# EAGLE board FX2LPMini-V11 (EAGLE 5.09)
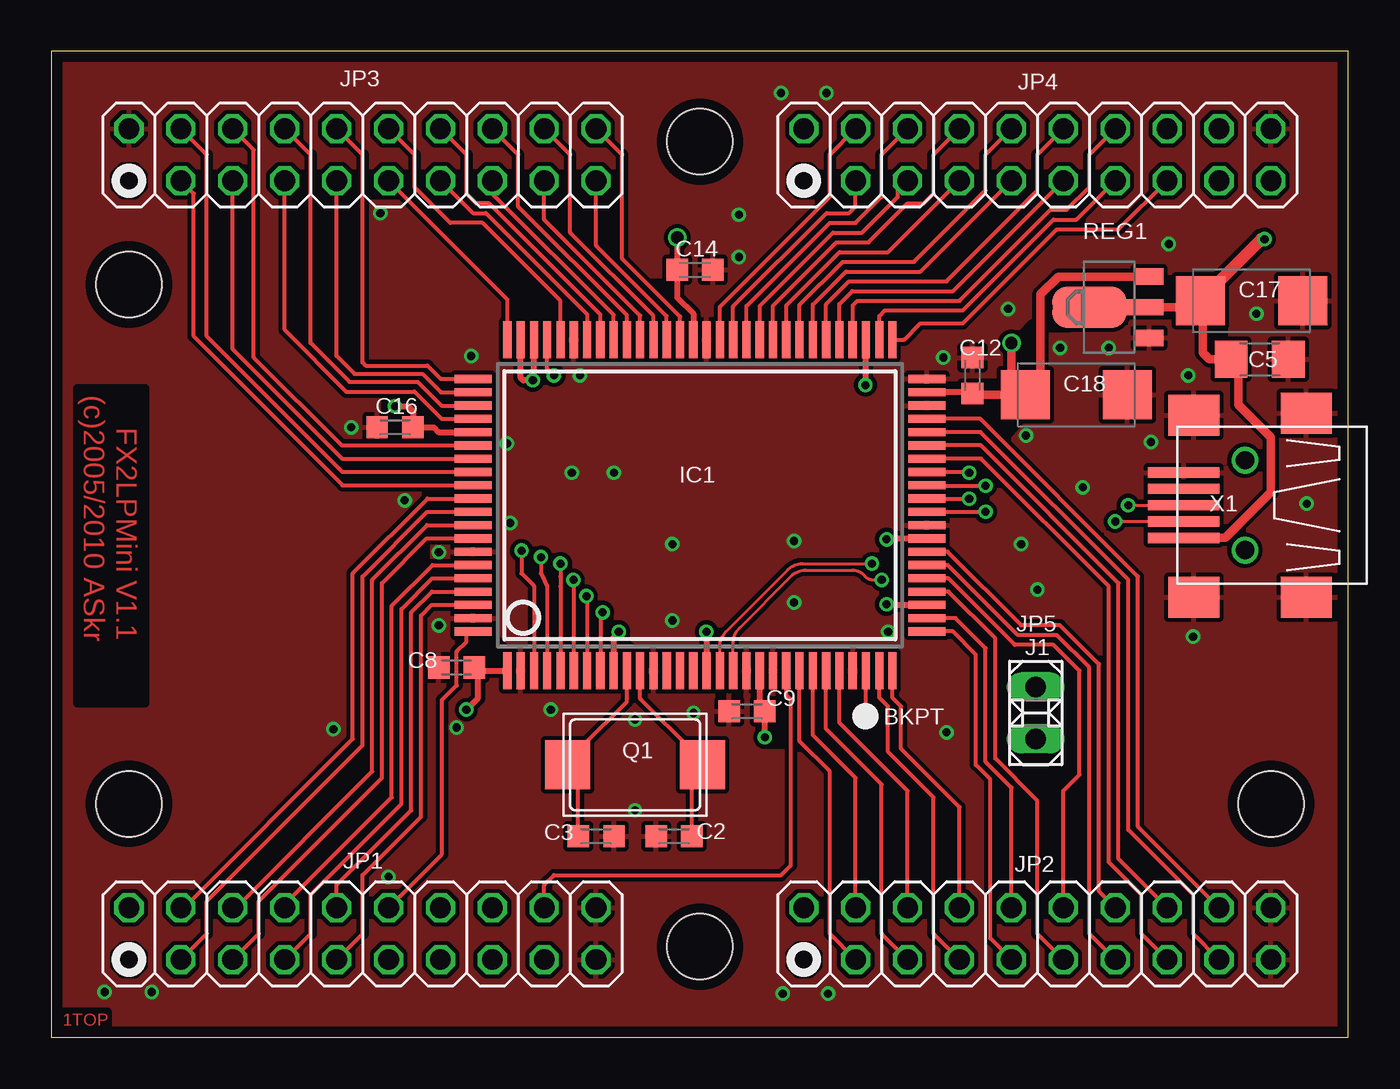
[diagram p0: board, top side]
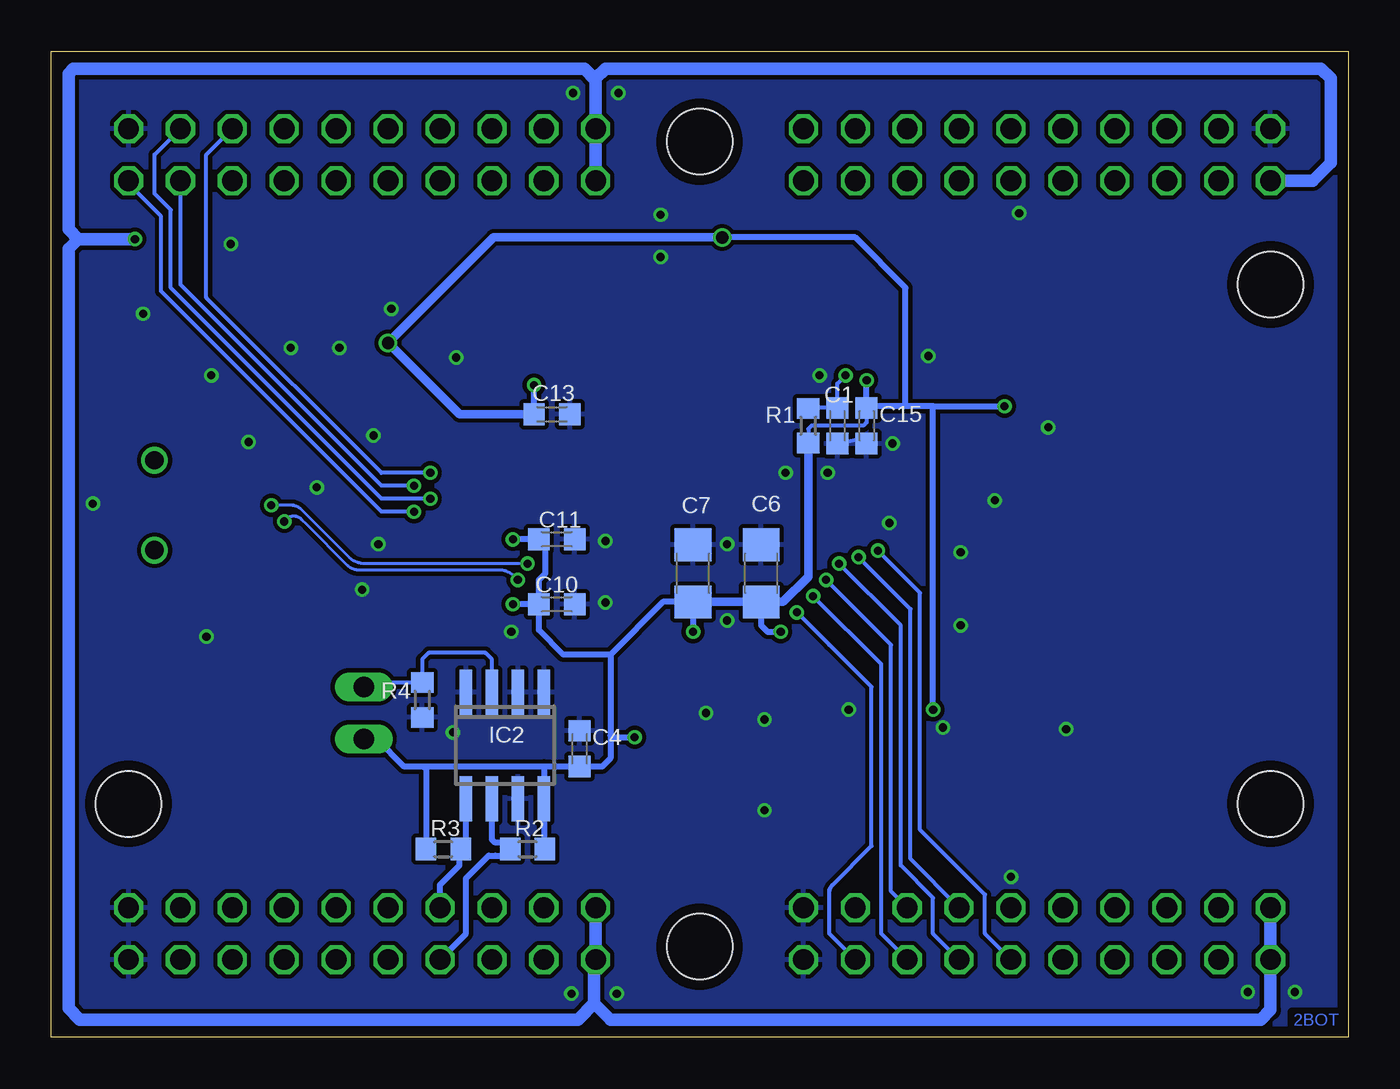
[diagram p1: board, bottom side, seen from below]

Size 63.48 x 48.25 mm. Coordinates in mm from the lower left corner, seen from the top.
Outline: 0,0 63.48,0 63.48,48.25 0,48.25 0,0
Copper layers (1*16): Top 0.035mm / dielectric 1.5mm / Bottom 0.035mm
Design rules "pcb-pool-2009": minimum track width 6mil, minimum drill 12mil, track to track 6mil, track to pad 6mil, pad to pad 6mil, via to via 6mil, smd to smd 6mil, copper to edge 20mil, drill to drill 8mil, minimum pad ring 8mil, minimum via ring 6mil, stop-mask expansion 3mil, vias tented up to drill 0mil, thermal gap 8mil
Holes 3.2 mm at 3.81,36.83 3.81,11.43 59.69,11.43 31.75,43.81 31.75,4.45
tRestrict: 25 lines
bRestrict: 5 lines

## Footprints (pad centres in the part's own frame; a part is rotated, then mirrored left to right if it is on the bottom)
B1,27 = smd 1.27 x 1.27: TP 0,0
C0603K = smd 1.05 x 1.08: 1 -0.875,0; 2 0.875,0
C1206 = smd 1.6 x 1.8: 1 -1.4,0; 2 1.4,0
SMC_C = smd 2.4 x 2.4: + -2.5,0; - 2.5,0
SQFP-R-14X20-100 = smd 0.4 x 1.8: 1 -9.425,-8.1; 2 -8.775,-8.1; 3 -8.125,-8.1; 4 -7.475,-8.1; 5 -6.825,-8.1; 6 -6.175,-8.1; 7 -5.525,-8.1; 8 -4.875,-8.1; 9 -4.225,-8.1; 10 -3.575,-8.1; 11 -2.925,-8.1; 12 -2.275,-8.1; 13 -1.625,-8.1; 14 -0.975,-8.1; 15 -0.325,-8.1; 16 0.325,-8.1; 17 0.975,-8.1; 18 1.625,-8.1; 19 2.275,-8.1; 20 2.925,-8.1; 21 3.575,-8.1; 22 4.225,-8.1; 23 4.875,-8.1; 24 5.525,-8.1; 25 6.175,-8.1; 26 6.825,-8.1; 27 7.475,-8.1; 28 8.125,-8.1; 29 8.775,-8.1; 30 9.425,-8.1; 51 9.425,8.1; 52 8.775,8.1; 53 8.125,8.1; 54 7.475,8.1; 55 6.825,8.1; 56 6.175,8.1; 57 5.525,8.1; 58 4.875,8.1; 59 4.225,8.1; 60 3.575,8.1; 61 2.925,8.1; 62 2.275,8.1; 63 1.625,8.1; 64 0.975,8.1; 65 0.325,8.1; 66 -0.325,8.1; 67 -0.975,8.1; 68 -1.625,8.1; 69 -2.275,8.1; 70 -2.925,8.1; 71 -3.575,8.1; 72 -4.225,8.1; 73 -4.875,8.1; 74 -5.525,8.1; 75 -6.175,8.1; 76 -6.825,8.1; 77 -7.475,8.1; 78 -8.125,8.1; 79 -8.775,8.1; 80 -9.425,8.1 | smd 1.8 x 0.4: 31 11.1,-6.175; 32 11.1,-5.525; 33 11.1,-4.875; 34 11.1,-4.225; 35 11.1,-3.575; 36 11.1,-2.925; 37 11.1,-2.275; 38 11.1,-1.625; 39 11.1,-0.975; 40 11.1,-0.325; 41 11.1,0.325; 42 11.1,0.975; 43 11.1,1.625; 44 11.1,2.275; 45 11.1,2.925; 46 11.1,3.575; 47 11.1,4.225; 48 11.1,4.875; 49 11.1,5.525; 50 11.1,6.175; 81 -11.1,6.175; 82 -11.1,5.525; 83 -11.1,4.875; 84 -11.1,4.225; 85 -11.1,3.575; 86 -11.1,2.925; 87 -11.1,2.275; 88 -11.1,1.625; 89 -11.1,0.975; 90 -11.1,0.325; 91 -11.1,-0.325; 92 -11.1,-0.975; 93 -11.1,-1.625; 94 -11.1,-2.275; 95 -11.1,-2.925; 96 -11.1,-3.575; 97 -11.1,-4.225; 98 -11.1,-4.875; 99 -11.1,-5.525; 100 -11.1,-6.175
SO-08 = smd 0.6 x 2.2: 1 -1.905,-2.6; 2 -0.635,-2.6; 3 0.635,-2.6; 4 1.905,-2.6; 5 1.905,2.6; 6 0.635,2.6; 7 -0.635,2.6; 8 -1.905,2.6
2X10 = drill 1.016 octagon: 1 -11.43,-1.27; 2 -11.43,1.27; 3 -8.89,-1.27; 4 -8.89,1.27; 5 -6.35,-1.27; 6 -6.35,1.27; 7 -3.81,-1.27; 8 -3.81,1.27; 9 -1.27,-1.27; 10 -1.27,1.27; 11 1.27,-1.27; 12 1.27,1.27; 13 3.81,-1.27; 14 3.81,1.27; 15 6.35,-1.27; 16 6.35,1.27; 17 8.89,-1.27; 18 8.89,1.27; 19 11.43,-1.27; 20 11.43,1.27
1X02 = drill 1.016 long: 1 -1.27,0; 2 1.27,0
AKKI_HLX-DB = smd 2.2 x 2.4: P$1 -3.3,0; P$2 3.3,0
R0603 = smd 1 x 1.1: 1 -0.85,0; 2 0.85,0
SOT89 = smd 0.8 x 1.4: 1 -1.499,-1.981; 3 1.499,-1.981 | smd 0.8 x 1.9: 2 0,-1.727 | smd 2.032 x 3.65: 2@1 0,0.94
USB-MB-S = smd 3.5 x 0.5: D+ 3,0; D- 3,0.8; GND 3,-1.6; ID 3,-0.8; VBUS 3,1.6 | smd 2.5 x 2: GND@1 -3,4.5; GND@2 2.5,4.5; GND@3 -3,-4.5; GND@4 2.5,-4.4 | drill 0.9 round: P$5 0,2.2; P$6 0,-2.2

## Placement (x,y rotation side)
BKPT  [B1,27]  39.85,15.72 0 top
C1  100n  [C0603K]  25,29.92 90 bottom
C2  15p  [C0603K]  30.48,9.84 0 top
C3  15p  [C0603K]  26.67,9.84 180 top
C4  100n  [C0603K]  37.62,14.13 90 bottom
C5  100n  [C1206]  59.13,33.18 0 top
C6  2u2  [C1206]  28.73,22.7 90 bottom
C7  2u2  [C1206]  32.07,22.7 90 bottom
C8  100n  [C0603K]  19.84,18.1 0 top
C9  100n  [C0603K]  34.05,15.95 0 top
C10  100n  [C0603K]  38.74,21.19 180 bottom
C11  100n  [C0603K]  38.73,24.37 180 bottom
C12  100n  [C0603K]  45.09,32.38 270 top
C13  100n  [C0603K]  38.97,30.48 180 bottom
C14  100n  [C0603K]  31.51,37.54 180 top
C15  100n  [C0603K]  23.57,29.92 90 bottom
C16  100n  [C0603K]  16.83,29.84 0 top
C17  15u;16V  [SMC_C]  58.74,36.04 0 top
C18  33u;6V3  [SMC_C]  50.16,31.43 0 top
IC1  CY7C68013A-100AXC  [SQFP-R-14X20-100]  31.75,26.04 0 top
IC2  24LC02  [SO-08]  41.27,14.29 180 bottom
J1  [JUMP]  48.18,15.87 0 top
JP1  [2X10]  15.24,5.08 0 top
JP2  [2X10]  48.26,5.08 0 top
JP3  [2X10]  15.24,43.18 0 top
JP4  [2X10]  48.26,43.18 0 top
JP5  [1X02]  48.18,15.87 90 top
Q1  24MHz  [AKKI_HLX-DB]  28.57,13.34 0 top
R1  100k  [R0603]  26.43,29.92 270 bottom
R2  4k7  [R0603]  40.16,9.21 0 bottom
R3  4k7  [R0603]  44.29,9.21 180 bottom
R4  100k  [R0603]  45.32,16.51 90 bottom
REG1  S817A33  [SOT89]  51.75,35.72 90 top
X1  AKKI_USB-MB-S  [USB-MB-S]  58.42,26.04 180 top

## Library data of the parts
BKPT = testpad
C1-C4 C8-C16 R1-R4 = rcl; SIZE: 0603
C5-C7 = rcl
C17 C18 = rcl; SIZE: C
IC1 Q1 REG1 X1 = Akki
IC2 = microchip
J1 = jumper
JP1-JP5 = pinhead

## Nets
!RD: IC1.31 JP2.9
!WR: IC1.32 JP2.10
+3V3: C4.1 C6.1 C7.1 C8.2 C9.2 C10.2 C11.2 C12.2 C13.2 C14.2 C15.2 C16.2 C18.+ IC1.1 IC1.9 IC1.16 IC1.20 IC1.33 IC1.38 IC1.49 IC1.53 IC1.66 IC1.78 IC1.79 IC1.85 IC2.8 JP5.1 R1.2 R2.2 R3.2 REG1.3
+UB: C5.1 C17.+ JP1.1 JP1.2 JP2.1 JP2.2 JP3.1 JP4.1 JP4.2 REG1.2 X1.VBUS
CLKOUT: IC1.100 JP1.12
CTL0: IC1.54 JP4.14
CTL1: IC1.55 JP4.11
CTL2: IC1.56 JP4.12
CTL3: IC1.51 JP4.15
CTL4: IC1.52 JP4.13
CTL5: IC1.76 JP3.12
FD0: IC1.34 JP2.11
FD1: IC1.35 JP2.12
FD2: IC1.36 JP2.13
FD3: IC1.37 JP2.14
FD4: IC1.44 JP2.15
FD5: IC1.45 JP2.16
FD6: IC1.46 JP2.17
FD7: IC1.47 JP2.18
FD8: IC1.80 JP3.11
FD9: IC1.81 JP3.10
FD10: IC1.82 JP3.9
FD11: IC1.83 JP3.8
FD12: IC1.95 JP1.8
FD13: IC1.96 JP1.7
FD14: IC1.97 JP1.10
FD15: IC1.98 JP1.9
GND: C1.1 C2.1 C3.1 C4.2 C5.2 C6.2 C7.2 C8.1 C9.1 C10.1 C11.1 C12.1 C13.1 C14.1 C15.1 C16.1 C17.- C18.- IC1.2 IC1.12 IC1.19 IC1.21 IC1.27 IC1.39 IC1.48 IC1.50 IC1.65 IC1.75 IC1.94 IC1.99 IC2.1 IC2.2 IC2.4 IC2.7 JP1.19 JP1.20 JP2.19 JP2.20 JP3.2 JP4.20 R4.1 REG1.1 X1.GND X1.GND@1 X1.GND@2 X1.GND@3 X1.GND@4
GPIF0: IC1.57 JP4.9
GPIF1: IC1.58 JP4.10
GPIF2: IC1.59 JP4.7
GPIF3: IC1.60 JP4.8
GPIF4: IC1.61 JP4.5
GPIF5: IC1.62 JP4.6
GPIF6: IC1.63 JP4.3
GPIF7: IC1.64 JP4.4
IFCLK: IC1.26 JP2.6
INT4: IC1.22 JP1.18
INT5: IC1.84 JP3.7
N$1: C1.2 IC1.77 R1.1
N$2: IC1.17 X1.D+
N$3: IC1.18 X1.D-
N$6: C2.2 IC1.11 Q1.P$2
N$7: C3.2 IC1.10 Q1.P$1
N$8: BKPT.TP IC1.28
N$13: IC2.3 JP5.2 R4.2
PA0: IC1.67 JP3.20
PA1: IC1.68 JP3.19
PA2: IC1.69 JP3.18
PA3: IC1.70 JP3.17
PA4: IC1.71 JP3.16
PA5: IC1.72 JP3.15
PA6: IC1.73 JP3.14
PA7: IC1.74 JP3.13
PE0: IC1.86 JP3.6
PE1: IC1.87 JP3.5
PE2: IC1.88 JP3.4
PE3: IC1.89 JP3.3
PE4: IC1.90 JP1.4
PE5: IC1.91 JP1.3
PE6: IC1.92 JP1.6
PE7/GPIF8: IC1.93 JP1.5
RDY0/SLRD: IC1.3 JP1.11
RDY1/SLRW: IC1.4 JP1.14
RDY2: IC1.5 JP1.13
RDY3: IC1.6 JP1.16
RDY4: IC1.7 JP1.15
RDY5: IC1.8 JP1.17
RXD0: IC1.41 JP4.18
RXD1: IC1.43 JP4.16
SCL: IC1.29 IC2.6 JP2.7 R2.1
SDA: IC1.30 IC2.5 JP2.8 R3.1
T0: IC1.23 JP2.3
T1: IC1.24 JP2.4
T2: IC1.25 JP2.5
TXD0: IC1.40 JP4.19
TXD1: IC1.42 JP4.17

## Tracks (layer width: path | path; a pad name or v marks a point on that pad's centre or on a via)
!RD
  Top 0.203: IC1.31 44.12,19.86 45.24,18.73 45.24,13.34 45.96,12.62 45.96,4.84 JP2.9
!WR
  Top 0.203: IC1.32 44.26,20.51 45.72,19.05 45.72,13.49 46.99,12.22 JP2.10
+3V3  (via drill 0.4, 0.6)
  Top 0.305: IC1.9 27.52,19.59 v27.78,19.84 | IC1.16 v32.08,19.84 v32.07,19.84 | IC1.20 34.67,16.21 C9.2 v34.93,14.69 v34.92,14.68 | IC1.49 45.03,31.56 C12.2 | IC1.66 31.43,35.41 30.64,36.2 30.64,37.07 C14.2 v30.64,39.13 | IC1.85 18.97,29.61 18.73,29.84 C16.2 | C16.2 | 20.88,17.93 IC1.1 | 20.88,17.93 C8.2 | IC1.38 40.92,24.41 v40.88,24.37 | IC1.33 40.91,21.16 v40.88,21.19 | IC1.53 39.88,32.1 v39.85,31.91 | IC1.78 23.62,32.2 v23.57,32.15 23.1,32.15 22.98,32.27 IC1.79 | C16.2 17.7,30.64 17.46,30.88 v16.83,30.88 | 20.88,17.93 20.88,16.59 v20.32,16.03
  Top 0.406: REG1.3 49.28,37.22 48.42,36.35 48.42,32.03 C18.+ | C18.+ 45.16,31.43 C12.2 | v46.99,33.97 46.99,32.27 C18.+
  Bottom 0.203: 39.37,9.26 R2.2 | R1.2 26.43,29.37 26.43,29.77 26.27,29.92 23.73,29.92 23.57,30.08 C15.2
  Bottom 0.305: 39.37,9.26 IC2.8 39.37,13.26 39.37,13.25 | v27.78,19.84 28.42,19.84 28.73,20.16 C6.1 | C6.1 | v32.07,19.84 C7.1 33.55,21.3 36.12,18.73 | C11.2 v40.88,24.37 | C11.2 | C10.2 v40.88,21.19 | v39.85,31.91 C13.2 | 39.37,13.25 C4.1 36.51,13.25 36.12,13.65 36.12,14.76 | JP5.1 47.55,14.61 46.19,13.25 45.24,13.25 | 39.37,13.25 45.24,13.25 | R3.2 45.14,13.15 45.24,13.25 | v23.57,32.15 C15.2 23.5,30.88 21.67,30.88 | 20.32,30.88 21.67,30.88 | 20.32,30.88 v16.83,30.88 | 21.67,30.88 21.67,36.67 24.13,39.13 v30.64,39.13 | C10.2 39.61,22.38 39.29,22.7 39.29,24.05 C11.2 | 36.12,18.73 36.12,14.76 | 36.12,18.73 38.42,18.73 39.61,19.93 C10.2 | v34.92,14.68 36.04,14.68 36.12,14.76 | v20.32,16.03 20.32,30.88 | 20.32,30.88
  Bottom 0.406: C7.1 C6.1 27.67,21.3 26.43,22.54 26.43,29.37 | C13.2 43.5,30.48 v46.99,33.97 41.83,39.13 v30.64,39.13
+UB  (via drill 0.4)
  Top 0.406: X1.VBUS 57.45,24.43 59.69,26.67 59.69,29.37 58.1,30.96 58.1,32.49 C5.1 56.67,33.18 56.36,33.5 56.36,35.44 56.08,35.72 | 56.08,35.72 REG1.2 | 56.08,35.72 C17.+ 56.2,36.08 56.2,36.2
  Top 0.61: 56.2,36.2 56.83,36.83 56.99,36.83 59.21,39.05 v59.37,39.05
  Bottom 0.61: 62.15,39.05 v59.37,39.05 62.15,39.05 | 62.15,39.05 62.63,38.58 62.63,1.43 62.07,0.87 37.7,0.87 36.91,1.67 | 62.15,39.05 62.63,39.53 62.63,47.15 62.39,47.39 37.39,47.39 36.83,46.83 | 36.83,46.83 JP4.2 JP4.1 | 36.83,46.83 36.83,46.91 36.35,47.39 1.35,47.39 0.87,46.91 0.87,42.78 1.75,41.91 JP3.1 | JP1.2 JP1.1 3.81,1.35 4.29,0.87 36.12,0.87 36.91,1.67 | 36.91,1.67 36.91,3.73 JP2.1 JP2.2
CLKOUT
  Top 0.203: IC1.100 20.63,19.84 20.32,19.84 20.32,19.37 19.84,18.89 19.84,17.22 19.13,16.51 19.13,8.97 JP1.12
CTL0
  Top 0.203: IC1.54 39.23,35.81 39.45,36.04 44.45,36.04 48.9,40.48 49.69,40.48 50.8,41.59 50.8,43.18 JP4.14
CTL1
  Top 0.203: IC1.55 38.58,35.88 39.21,36.51 44.13,36.51 JP4.11
CTL2
  Top 0.203: IC1.56 37.92,35.86 39.05,36.99 43.81,36.99 48.26,41.43 48.26,43.18 JP4.12
CTL3
  Top 0.203: IC1.51 41.75,34.13 42.55,34.92 44.61,34.92 49.21,39.53 52.23,39.53 JP4.15
CTL4
  Top 0.203: IC1.52 40.52,35.29 40.8,35.56 44.61,35.56 49.05,40.01 50.16,40.01 JP4.13
CTL5
  Top 0.203: JP3.12 17.78,43.18 17.78,41.59 19.53,39.85 21.11,39.85 24.93,36.03 IC1.76
FD0
  Top 0.203: IC1.34 43.91,21.81 46.2,19.53 46.2,13.65 48.26,11.59 48.26,5.08 JP2.11
FD1
  Top 0.203: JP2.12 49.53,12.06 50.32,12.86 50.32,17.94 49.05,19.21 47.15,19.21 43.9,22.46 IC1.35
FD2
  Top 0.203: JP2.13 | IC1.36 43.88,23.11 47.31,19.68 49.21,19.68 50.8,18.1 50.8,5.08 JP2.13
FD3
  Top 0.203: IC1.37 43.87,23.76 47.47,20.16 49.37,20.16 51.28,18.26 51.28,7.14 JP2.14
FD4
  Top 0.203: IC1.44 45.51,28.31 51.75,22.07 51.75,8.57 53.34,6.99 53.34,5.08 JP2.15
FD5
  Top 0.203: IC1.45 45.49,28.96 52.23,22.23 52.23,8.73 JP2.16 | JP2.16
FD6
  Top 0.203: IC1.46 45.48,29.61 52.7,22.38 52.7,10.16 55.88,6.99 | JP2.17 55.88,5.08 55.88,6.99 | 55.88,6.99
FD7
  Top 0.203: IC1.47 45.46,30.26 53.18,22.54 53.18,10.32 JP2.18 | JP2.18
FD8
  Top 0.203: IC1.80 22.32,36.09 JP3.11
FD9
  Top 0.203: IC1.81 19.07,32.21 18.41,32.86 15.4,32.86 15.24,33.02 15.24,43.18 JP3.10
FD10
  Top 0.203: IC1.82 19.08,31.56 18.18,32.46 14.84,32.47 13.97,33.34 JP3.9
FD11
  Top 0.203: IC1.83 19.1,30.91 17.94,32.07 14.61,32.07 12.7,33.97 12.7,43.18 JP3.8
FD12
  Top 0.203: JP1.8 11.43,6.51 16.67,11.75 16.67,21.11 18.66,23.11 IC1.95
FD13
  Top 0.203: JP1.7 12.7,5.08 12.7,6.99 17.14,11.43 17.14,20.95 18.65,22.46 IC1.96
FD14
  Top 0.203: JP1.10 13.97,7.46 17.62,11.11 17.62,20.8 18.64,21.81 IC1.97
FD15
  Top 0.203: JP1.9 15.24,5.08 15.24,7.94 18.1,10.79 18.1,20.64 18.62,21.16 IC1.98
GND  (via drill 0.4)
  Bottom 0.203: C1.1 23.18,29.45 C15.1
  other vias: 28.57,15.56 28.57,11.11 24.45,16.03 31.43,15.88 14.68,29.84 47.47,24.13 48.26,21.91 36.35,24.29 36.35,21.27 25.88,32.38 18.97,20.16 17.3,26.27 61.44,26.11 55.64,32.38 51.75,33.73 50.48,26.91 43.66,33.26 49.37,33.73 47.7,29.45 16.51,7.86 19.84,15.16 4.92,2.22 2.62,2.22 38.02,2.14 35.8,2.14 37.94,46.2 35.72,46.2 33.66,38.18 33.66,40.24 18.97,23.73 22.3,29.05 22.46,25.16 25.48,27.62 27.54,27.62 30.4,24.13 30.4,20.4 55.88,19.61 53.82,29.13 58.98,35.4 54.69,38.81 46.83,35.64 20.56,33.34 16.11,40.32 40.96,19.84 43.81,14.92 13.81,15.08
  pour Top (isolate 0.203): 33.97,16.51 23.18,16.51 23.18,8.57 33.97,8.57
  pour Bottom (isolate 0.203): 23.97,16.51 32.07,16.51 32.07,10.48 23.97,10.48
  pour Top (isolate 0.203): 0.64,47.62 62.87,47.62 62.87,0.64 0.64,0.64
  pour Bottom (isolate 0.203): 0.64,47.62 62.87,47.62 62.87,0.64 0.64,0.64
GPIF0
  Top 0.203: IC1.57 37.27,35.85 38.89,37.47 42.55,37.47 JP4.9
GPIF1
  Top 0.203: IC1.58 36.62,35.83 38.73,37.94 42.23,37.94 45.72,41.43 45.72,43.18 JP4.10
GPIF2
  Top 0.203: IC1.59 35.98,35.82 38.58,38.42 40.96,38.42 JP4.7
GPIF3
  Top 0.203: IC1.60 35.33,35.8 38.42,38.89 40.01,38.89 41.91,40.8 42.7,40.8 43.18,41.27 43.18,43.18 JP4.8
GPIF4
  Top 0.203: IC1.61 34.67,35.79 38.26,39.37 39.69,39.37 41.43,41.12 41.43,41.43 JP4.5
GPIF5
  Top 0.203: IC1.62 34.02,35.77 38.1,39.85 39.37,39.85 40.64,41.12 40.64,43.18 JP4.6
GPIF6
  Top 0.203: IC1.63 33.38,35.76 37.94,40.32 39.05,40.32 39.37,40.64 JP4.3
GPIF7
  Top 0.203: IC1.64 32.73,35.74 36.67,39.69 | 36.67,39.69 | 36.67,39.69 38.1,41.12 38.1,43.18 JP4.4
IFCLK
  Top 0.203: JP2.6 41.91,12.06 38.58,15.4 IC1.26
INT4
  Top 0.203: JP1.18 24.13,7.46 24.61,7.94 35.72,7.94 36.2,8.41 36.2,16.51 35.98,16.73 IC1.22
INT5
  Top 0.203: IC1.84 19.11,30.26 17.78,31.59 14.45,31.59 11.43,34.61 JP3.7
N$1  (via drill 0.4)
  Top 0.203: IC1.77 24.27,32.72 v24.61,32.38
  Bottom 0.203: v24.61,32.38 25,31.99 C1.2 26.41,30.8 R1.1
N$2  (via drill 0.4)
  Top 0.152: IC1.17 32.73,19.13 arc-45 33.02,19.85 36.06,22.88 arc-45 36.77,23.18 v40.16,23.18 | v52.7,26.04 X1.D+ | v52.7,26.04
  Bottom 0.152: v40.16,23.18 48.16,23.18 arc45 48.88,23.48 51.21,25.81 arc-45 51.75,26.04 v52.7,26.04
N$3  (via drill 0.4)
  Top 0.152: IC1.18 33.38,19.3 arc-45 33.67,20.02 36.22,22.56 arc-45 36.93,22.86 39.21,22.86 arc-53 39.85,22.54 arc45 40.23,22.38 v40.64,22.38 | v52.07,25.24 55.41,25.24
  Top 0.203: 55.41,25.24 arc-45 X1.D-
  Bottom 0.152: v40.64,22.38 40.82,22.56 arc-45 41.54,22.86 48.42,22.86 arc45 48.96,23.08 50.96,25.08 51.21,25.33 arc-102 v52.07,25.24
N$6
  Top 0.203: IC1.11 28.82,16.58 31.43,13.97 31.43,13.78 Q1.P$2 31.36,12.81 C2.2
N$7
  Top 0.203: IC1.10 28.18,16.43 26.04,14.29 26.04,14.1 Q1.P$1 25.8,12.81 C3.2
N$8
  Top 0.203: 39.56,15.85 39.72,15.85 BKPT.TP 39.88,15.74 IC1.28
N$13
  Bottom 0.203: IC2.3 41.91,18.49 42.23,18.81 45.01,18.81 45.32,18.49 R4.2 | R4.2 | R4.2 47.97,17.36 JP5.2
PA0
  Top 0.203: IC1.67 30.77,35.27 27.94,38.1 27.94,43.18 JP3.20
PA1
  Top 0.203: IC1.68 30.12,35.28 26.67,38.73 JP3.19
PA2
  Top 0.203: IC1.69 29.48,35.3 25.4,39.37 25.4,43.18 JP3.18
PA3
  Top 0.203: IC1.70 28.82,35.31 24.13,40.01 JP3.17
PA4
  Top 0.203: IC1.71 28.18,35.33 22.86,40.64 22.86,43.18 JP3.16
PA5
  Top 0.203: IC1.72 27.52,35.34 21.59,41.27 JP3.15
PA6
  Top 0.203: IC1.73 26.88,35.35 21.43,40.8 20.8,40.8 20.32,41.27 20.32,43.18 JP3.14
PA7
  Top 0.203: IC1.74 26.23,35.37 21.27,40.32 20.64,40.32 JP3.13
PE0
  Top 0.203: IC1.86 14.22,28.96 9.92,33.26 9.92,43.42 JP3.6
PE1
  Top 0.203: IC1.87 14.23,28.31 8.89,33.66 JP3.5
PE2
  Top 0.203: IC1.88 14.25,27.66 7.62,34.29 7.62,43.18 JP3.4
PE3
  Top 0.203: IC1.89 14.27,27.01 6.99,34.29 6.99,41.27 JP3.3
PE4
  Top 0.203: JP1.4 6.51,6.35 14.76,14.61 14.76,22.7 18.42,26.36 IC1.90
PE5
  Top 0.203: JP1.3 7.62,5.08 7.62,6.67 15.24,14.29 15.24,22.54 18.41,25.71 IC1.91
PE6
  Top 0.203: JP1.6 9.05,6.35 15.72,13.02 15.72,22.38 18.39,25.06 IC1.92
PE7/GPIF8
  Top 0.203: JP1.5 10.16,5.08 10.16,6.67 16.19,12.7 16.19,22.23 18.38,24.41 IC1.93
RDY0/SLRD  (via drill 0.4)
  Top 0.203: 23.02,23.65 v23.02,23.81 23.02,22.7 23.62,22.09 IC1.3
  Bottom 0.203: JP1.11 17.78,5.08 17.78,6.99 20.95,10.16 20.95,21.75 v23.02,23.81 23.02,23.65
RDY1/SLRW  (via drill 0.4)
  Top 0.203: IC1.4 24.27,22.08 23.97,22.7 v23.97,23.5
  Bottom 0.203: JP1.14 21.43,8.73 21.43,20.95 v23.97,23.5
RDY2  (via drill 0.4)
  Top 0.203: IC1.5 24.93,22.07 24.92,22.54 v24.92,23.18
  Bottom 0.203: JP1.13 20.32,5.08 20.32,6.83 21.91,8.41 21.91,20.16 v24.92,23.18
RDY3  (via drill 0.4)
  Top 0.203: 25.56,22.23 v25.56,22.38 25.57,22.37 IC1.6
  Bottom 0.203: JP1.16 22.38,7.14 22.38,19.21 v25.56,22.38
RDY4  (via drill 0.4)
  Top 0.203: IC1.7 26.23,21.56 v26.19,21.59
  Bottom 0.203: JP1.15 22.86,5.08 22.86,18.26 v26.19,21.59
RDY5  (via drill 0.4)
  Top 0.203: IC1.8 26.88,20.75 v26.99,20.8
  Bottom 0.203: JP1.17 25.4,5.08 25.4,7.09 arc45 25.25,7.45 23.34,9.37 23.34,17.14 25.4,19.21 v26.99,20.8
RXD0  (via drill 0.4)
  Top 0.203: IC1.41 v44.93,26.35
  Bottom 0.203: v44.93,26.35 47.31,26.35 57.63,36.67 57.63,40.48 58.42,41.27 58.42,43.18 JP4.18
RXD1  (via drill 0.4)
  Top 0.203: IC1.43 44.89,27.66 v44.93,27.62
  Bottom 0.203: v44.93,27.62 47.31,27.62 55.88,36.2 55.88,43.18 JP4.16
SCL
  Top 0.203: JP2.7 43.18,5.08 43.18,11.75 40.96,13.97 40.96,16.19 40.52,16.62 IC1.29
  Bottom 0.203: 41.01,9.53 R2.1 41.27,8.89
  Bottom 0.305: IC2.6 41.91,9.68 41.75,9.53 41.01,9.53 | 41.27,8.89 41.75,8.89 42.07,8.89 43.18,7.78 43.18,5.08 JP2.7
SDA
  Top 0.203: JP2.8 44.45,11.27 41.59,14.13 41.59,16.19 41.17,16.61 IC1.30
  Bottom 0.203: R3.1 43.18,9.47 43.18,9.21 43.5,8.89
  Bottom 0.305: 43.18,9.47 IC2.5 | 43.5,8.89 43.5,8.41 44.45,7.46 JP2.8
T0
  Top 0.203: JP2.3 38.1,5.08 38.1,13.02 36.62,14.49 IC1.23
T1
  Top 0.203: JP2.4 39.37,12.7 37.27,14.79 IC1.24
T2
  Top 0.203: JP2.5 40.64,5.08 40.64,12.38 37.92,15.1 IC1.25
TXD0  (via drill 0.4)
  Top 0.203: IC1.40 v45.72,25.72
  Bottom 0.203: v45.72,25.72 47.31,25.72 58.1,36.51 58.1,40.16 59.69,41.75 JP4.19
TXD1  (via drill 0.4)
  Top 0.203: IC1.42 42.87,26.99 v45.72,26.99
  Bottom 0.203: JP4.17 57.15,36.83 47.31,26.99 v45.72,26.99

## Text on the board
Top: (c)2005/2010 ASkr | FX2LPMini V1.1 | 1TOP
Bottom: 2BOT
